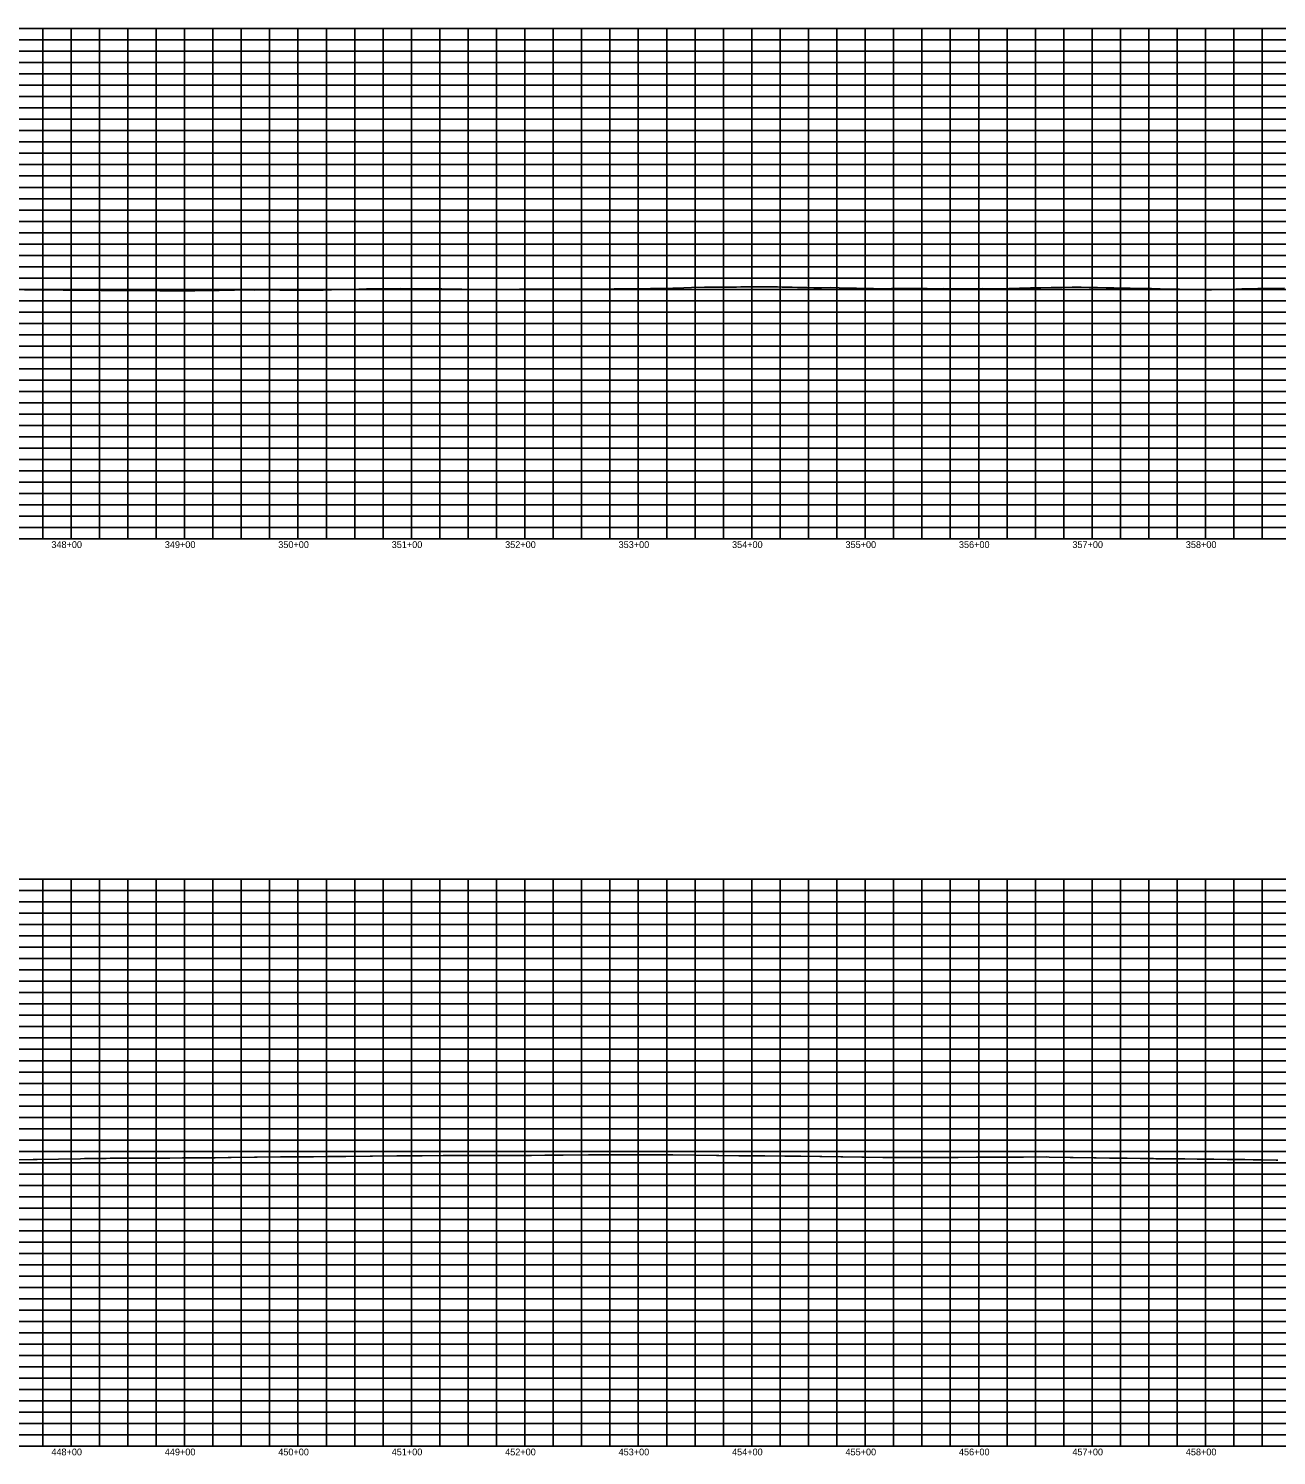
# Model space of a CAD drawing. Extents: x 1399671 to 1408349, y 1930471 to 1933387.
# Drawn here: x 1405087 to 1406187, y 1930471 to 1931729 of the extents above; entities that cross this region are included whole.
import ezdxf

# ---------------------------------------------------------------- set-up
doc = ezdxf.new("R2010")
doc.units = 0
for name, color, linetype in [('R_Exist Surface', 7, 'Continuous'), ('R_Grid', 7, 'Continuous'), ('R_Grid Annot', 7, 'Continuous')]:
    doc.layers.add(name, color=color, linetype=linetype)

msp = doc.modelspace()

# ---------------------------------------------------------------- linework, layer by layer
at = {"layer": 'R_Exist Surface'}
for points in [[(1405083.2, 1931498.2), (1405090.4, 1931498.1), (1405100.3, 1931498), (1405105.2, 1931498.2), (1405117.3, 1931498), (1405119.7, 1931498), (1405129.1, 1931497.8), (1405133.3, 1931497.9), (1405133.9, 1931497.8), (1405150.7, 1931497.6), (1405152.8, 1931497.6), (1405153, 1931497.6), (1405171, 1931497.6), (1405172.4, 1931497.6), (1405186.4, 1931497.5), (1405187.6, 1931497.5), (1405201.8, 1931497.5), (1405202.8, 1931497.4), (1405217.3, 1931497.4), (1405218, 1931497.4), (1405232.8, 1931497.3), (1405233.2, 1931497.3), (1405248.3, 1931497.5), (1405251.5, 1931497.6), (1405254.8, 1931497.7), (1405268.1, 1931498), (1405273.3, 1931498.2), (1405273.4, 1931498.2), (1405285.8, 1931497.9), (1405290.3, 1931498.1), (1405295.3, 1931498.1), (1405308.3, 1931497.8), (1405312.1, 1931497.8), (1405325.2, 1931497.9), (1405329.3, 1931497.9), (1405341.9, 1931497.9), (1405346.3, 1931497.9), (1405361, 1931498.5), (1405365.7, 1931498.6), (1405370.7, 1931498.6), (1405384.5, 1931499.1), (1405390, 1931499.2), (1405399.7, 1931499.2), (1405405.4, 1931499.2), (1405414.8, 1931499.3), (1405420.5, 1931499.2), (1405430.3, 1931499.2), (1405435.7, 1931499.2), (1405445.8, 1931499.2), (1405450.9, 1931499.2), (1405463.9, 1931498.8), (1405468.5, 1931498.8), (1405482.5, 1931498.5), (1405488.7, 1931498.5), (1405500.7, 1931498.6), (1405508.2, 1931498.6), (1405519.5, 1931498.7), (1405528.3, 1931498.7), (1405542.2, 1931498.7), (1405549.5, 1931498.7), (1405564.4, 1931498.7), (1405567.9, 1931498.7), (1405584.4, 1931498.9), (1405589, 1931498.9), (1405603, 1931499.1), (1405608.5, 1931499.1), (1405614.1, 1931499), (1405626.8, 1931499.2), (1405634.8, 1931499.4), (1405645.6, 1931499.5), (1405654.6, 1931499.8), (1405664.4, 1931500), (1405671.2, 1931500.2), (1405682.4, 1931500.5), (1405687.8, 1931500.6), (1405696.8, 1931500.6), (1405701.3, 1931500.7), (1405710.8, 1931500.7), (1405714.6, 1931500.8), (1405724.4, 1931500.8), (1405734.3, 1931500.9), (1405737.4, 1931500.8), (1405747, 1931500.8), (1405750.9, 1931500.6), (1405759.8, 1931500.7), (1405764.6, 1931500.4), (1405772.7, 1931500.4), (1405778.9, 1931500.1), (1405785.8, 1931500.1), (1405793.9, 1931500.2), (1405801.2, 1931499.9), (1405808.1, 1931499.6), (1405816.4, 1931499.7), (1405823.5, 1931499.4), (1405831.4, 1931499.5), (1405838.8, 1931499.2), (1405847.3, 1931499.3), (1405855, 1931499.3), (1405863.9, 1931499.4), (1405869.6, 1931499.3), (1405878.7, 1931499.3), (1405884.1, 1931499.2), (1405893.4, 1931499.3), (1405898.7, 1931499.2), (1405903.8, 1931499.1), (1405919.1, 1931499.1), (1405927.2, 1931499.3), (1405942.2, 1931499.2), (1405950.7, 1931499.4), (1405960.3, 1931499.6), (1405970, 1931499.9), (1405978.9, 1931500), (1405988.1, 1931500.2), (1405997.8, 1931500.4), (1406006.6, 1931500.6), (1406014.6, 1931500.5), (1406021.5, 1931500.4), (1406029, 1931500.2), (1406036.5, 1931500.1), (1406043.3, 1931500), (1406051.5, 1931499.8), (1406057.7, 1931499.7), (1406066.6, 1931499.5), (1406076.5, 1931499.3), (1406084.1, 1931499.1), (1406094.2, 1931498.9), (1406101.3, 1931498.7), (1406111.6, 1931498.5), (1406113.4, 1931498.4), (1406124.4, 1931498.2), (1406129.5, 1931498.2), (1406145.2, 1931498.5), (1406151, 1931498.9), (1406151, 1931498.9), (1406156.2, 1931499), (1406170.2, 1931499.3), (1406176.5, 1931499.3), (1406180.9, 1931499.3), (1406193.7, 1931499.6)], [(1405071.7, 1930731.2), (1405090.8, 1930731.5), (1405094.2, 1930731.5), (1405113.2, 1930731.9), (1405132.4, 1930732.1), (1405135.9, 1930732.2), (1405155.2, 1930732.4), (1405158.5, 1930732.5), (1405170.1, 1930732.5), (1405173.3, 1930732.5), (1405184.9, 1930732.6), (1405196.4, 1930732.6), (1405199.6, 1930732.6), (1405211.2, 1930732.7), (1405222.4, 1930732.8), (1405224.1, 1930732.8), (1405225.7, 1930732.8), (1405236.9, 1930732.9), (1405238.5, 1930732.9), (1405249.7, 1930733), (1405251.3, 1930733), (1405262.6, 1930733.1), (1405265.2, 1930733.1), (1405285.8, 1930733.4), (1405288.1, 1930733.4), (1405308.9, 1930733.7), (1405310.1, 1930733.7), (1405322.8, 1930733.8), (1405324, 1930733.8), (1405336.7, 1930733.9), (1405337.9, 1930733.9), (1405350.6, 1930734.1), (1405351.8, 1930734.1), (1405364.4, 1930734.2), (1405366.5, 1930734.2), (1405387.9, 1930734.5), (1405390, 1930734.5), (1405411.4, 1930734.7), (1405413.2, 1930734.7), (1405431.8, 1930734.8), (1405433.8, 1930734.8), (1405452.2, 1930734.9), (1405453.7, 1930734.9), (1405465.3, 1930734.9), (1405466.7, 1930734.9), (1405478.3, 1930734.9), (1405490.1, 1930734.9), (1405491.3, 1930734.9), (1405503.2, 1930734.9), (1405504.4, 1930734.9), (1405516.2, 1930735), (1405517.2, 1930735), (1405529, 1930735.1), (1405530.1, 1930735.1), (1405541.9, 1930735.3), (1405542.9, 1930735.3), (1405544, 1930735.3), (1405555.8, 1930735.4), (1405557.8, 1930735.4), (1405580.2, 1930735.5), (1405602.5, 1930735.5), (1405604.6, 1930735.5), (1405626.4, 1930735.5), (1405628.6, 1930735.5), (1405630.7, 1930735.5), (1405652.5, 1930735.5), (1405654.5, 1930735.5), (1405673.8, 1930735.2), (1405693, 1930735), (1405695.1, 1930735), (1405712.8, 1930734.8), (1405714.5, 1930734.8), (1405732.2, 1930734.6), (1405733.9, 1930734.6), (1405735.7, 1930734.6), (1405753.3, 1930734.5), (1405753.8, 1930734.5), (1405758.3, 1930734.4), (1405766.4, 1930734.5), (1405767.3, 1930734.5), (1405784.2, 1930734.2), (1405785.9, 1930734.2), (1405802.7, 1930733.9), (1405804.4, 1930733.9), (1405821.3, 1930733.6), (1405822.9, 1930733.6), (1405839.8, 1930733.3), (1405841.4, 1930733.2), (1405856.3, 1930733.3), (1405857.6, 1930733.3), (1405872.6, 1930733.3), (1405873.8, 1930733.3), (1405888.9, 1930733.3), (1405890, 1930733.3), (1405891, 1930733.3), (1405906.2, 1930733.3), (1405922.2, 1930733.4), (1405923.2, 1930733.4), (1405939.3, 1930733.6), (1405939.8, 1930733.6), (1405940.8, 1930733.6), (1405961.9, 1930733.6), (1405963.7, 1930733.6), (1405983.9, 1930733.7), (1405986.4, 1930733.6), (1406004.8, 1930733.3), (1406007.6, 1930733.2), (1406025.8, 1930732.8), (1406027.7, 1930732.8), (1406039.4, 1930732.7), (1406041.4, 1930732.6), (1406053, 1930732.5), (1406055, 1930732.5), (1406066.7, 1930732.3), (1406078.2, 1930732.2), (1406080.3, 1930732.1), (1406091.1, 1930732.1), (1406093.1, 1930732), (1406103.9, 1930732), (1406105.9, 1930732), (1406116.7, 1930731.9), (1406118.7, 1930731.9), (1406122.5, 1930731.8), (1406129.5, 1930731.8), (1406131.5, 1930731.8), (1406143.1, 1930731.6), (1406144.3, 1930731.6), (1406145.2, 1930731.6), (1406156.9, 1930731.4), (1406158.9, 1930731.4), (1406166.1, 1930731.2), (1406170.7, 1930731.2), (1406172.6, 1930731.2), (1406174.5, 1930731.1), (1406186.3, 1930731), (1406188, 1930730.9)]]:
    msp.add_lwpolyline(points, dxfattribs=at)
at = {"layer": 'R_Grid'}
for p, q in [((1400324.2, 1931728.6), (1408324.2, 1931728.6)), ((1400324.2, 1931728.6), (1408324.2, 1931728.6)), ((1405099.2, 1931278.6), (1405099.2, 1931728.6)), ((1405124.2, 1931278.6), (1405124.2, 1931728.6)), ((1405149.2, 1931278.6), (1405149.2, 1931728.6)), ((1405174.2, 1931278.6), (1405174.2, 1931728.6)), ((1405199.2, 1931278.6), (1405199.2, 1931728.6)), ((1405224.2, 1931278.6), (1405224.2, 1931728.6)), ((1405249.2, 1931278.6), (1405249.2, 1931728.6)), ((1405274.2, 1931278.6), (1405274.2, 1931728.6)), ((1405299.2, 1931278.6), (1405299.2, 1931728.6)), ((1405324.2, 1931278.6), (1405324.2, 1931728.6)), ((1405349.2, 1931278.6), (1405349.2, 1931728.6)), ((1405374.2, 1931278.6), (1405374.2, 1931728.6)), ((1405399.2, 1931278.6), (1405399.2, 1931728.6)), ((1405424.2, 1931278.6), (1405424.2, 1931728.6)), ((1405449.2, 1931278.6), (1405449.2, 1931728.6)), ((1405474.2, 1931278.6), (1405474.2, 1931728.6)), ((1405499.2, 1931278.6), (1405499.2, 1931728.6)), ((1405524.2, 1931278.6), (1405524.2, 1931728.6)), ((1405549.2, 1931278.6), (1405549.2, 1931728.6)), ((1405574.2, 1931278.6), (1405574.2, 1931728.6)), ((1405599.2, 1931278.6), (1405599.2, 1931728.6)), ((1405624.2, 1931278.6), (1405624.2, 1931728.6)), ((1405649.2, 1931278.6), (1405649.2, 1931728.6)), ((1405674.2, 1931278.6), (1405674.2, 1931728.6)), ((1405699.2, 1931278.6), (1405699.2, 1931728.6)), ((1405724.2, 1931278.6), (1405724.2, 1931728.6)), ((1405749.2, 1931278.6), (1405749.2, 1931728.6)), ((1405774.2, 1931278.6), (1405774.2, 1931728.6)), ((1405799.2, 1931278.6), (1405799.2, 1931728.6)), ((1405824.2, 1931278.6), (1405824.2, 1931728.6)), ((1405849.2, 1931278.6), (1405849.2, 1931728.6)), ((1405874.2, 1931278.6), (1405874.2, 1931728.6)), ((1405899.2, 1931278.6), (1405899.2, 1931728.6)), ((1405924.2, 1931278.6), (1405924.2, 1931728.6)), ((1405949.2, 1931278.6), (1405949.2, 1931728.6)), ((1405974.2, 1931278.6), (1405974.2, 1931728.6)), ((1405999.2, 1931278.6), (1405999.2, 1931728.6)), ((1406024.2, 1931278.6), (1406024.2, 1931728.6)), ((1406049.2, 1931278.6), (1406049.2, 1931728.6)), ((1406074.2, 1931278.6), (1406074.2, 1931728.6)), ((1406099.2, 1931278.6), (1406099.2, 1931728.6)), ((1406124.2, 1931278.6), (1406124.2, 1931728.6)), ((1406149.2, 1931278.6), (1406149.2, 1931728.6)), ((1406174.2, 1931278.6), (1406174.2, 1931728.6)), ((1400324.2, 1931718.6), (1408324.2, 1931718.6)), ((1400324.2, 1931708.6), (1408324.2, 1931708.6)), ((1400324.2, 1931698.6), (1408324.2, 1931698.6)), ((1400324.2, 1931688.6), (1408324.2, 1931688.6)), ((1400324.2, 1931678.6), (1408324.2, 1931678.6)), ((1400324.2, 1931668.6), (1408324.2, 1931668.6)), ((1400324.2, 1931658.6), (1408324.2, 1931658.6)), ((1400324.2, 1931648.6), (1408324.2, 1931648.6)), ((1400324.2, 1931638.6), (1408324.2, 1931638.6)), ((1400324.2, 1931628.6), (1408324.2, 1931628.6)), ((1400324.2, 1931618.6), (1408324.2, 1931618.6)), ((1400324.2, 1931608.6), (1408324.2, 1931608.6)), ((1400324.2, 1931598.6), (1408324.2, 1931598.6)), ((1400324.2, 1931588.6), (1408324.2, 1931588.6)), ((1400324.2, 1931578.6), (1408324.2, 1931578.6)), ((1400324.2, 1931568.6), (1408324.2, 1931568.6)), ((1400324.2, 1931558.6), (1408324.2, 1931558.6)), ((1400324.2, 1931548.6), (1408324.2, 1931548.6)), ((1400324.2, 1931538.6), (1408324.2, 1931538.6)), ((1400324.2, 1931528.6), (1408324.2, 1931528.6)), ((1400324.2, 1931518.6), (1408324.2, 1931518.6)), ((1400324.2, 1931508.6), (1408324.2, 1931508.6)), ((1400324.2, 1931498.6), (1408324.2, 1931498.6)), ((1400324.2, 1931488.6), (1408324.2, 1931488.6)), ((1400324.2, 1931478.6), (1408324.2, 1931478.6)), ((1400324.2, 1931468.6), (1408324.2, 1931468.6)), ((1400324.2, 1931458.6), (1408324.2, 1931458.6)), ((1400324.2, 1931448.6), (1408324.2, 1931448.6)), ((1400324.2, 1931438.6), (1408324.2, 1931438.6)), ((1400324.2, 1931428.6), (1408324.2, 1931428.6)), ((1400324.2, 1931418.6), (1408324.2, 1931418.6)), ((1400324.2, 1931408.6), (1408324.2, 1931408.6)), ((1400324.2, 1931398.6), (1408324.2, 1931398.6)), ((1400324.2, 1931388.6), (1408324.2, 1931388.6)), ((1400324.2, 1931378.6), (1408324.2, 1931378.6)), ((1400324.2, 1931368.6), (1408324.2, 1931368.6)), ((1400324.2, 1931358.6), (1408324.2, 1931358.6)), ((1400324.2, 1931348.6), (1408324.2, 1931348.6)), ((1400324.2, 1931338.6), (1408324.2, 1931338.6)), ((1400324.2, 1931328.6), (1408324.2, 1931328.6)), ((1400324.2, 1931318.6), (1408324.2, 1931318.6)), ((1400324.2, 1931308.6), (1408324.2, 1931308.6)), ((1400324.2, 1931298.6), (1408324.2, 1931298.6)), ((1400324.2, 1931288.6), (1408324.2, 1931288.6)), ((1400324.2, 1931278.6), (1408324.2, 1931278.6)), ((1400324.2, 1930978.6), (1407124.2, 1930978.6)), ((1400324.2, 1930978.6), (1407124.2, 1930978.6)), ((1405099.2, 1930478.6), (1405099.2, 1930978.6)), ((1405124.2, 1930478.6), (1405124.2, 1930978.6)), ((1405149.2, 1930478.6), (1405149.2, 1930978.6)), ((1405174.2, 1930478.6), (1405174.2, 1930978.6)), ((1405199.2, 1930478.6), (1405199.2, 1930978.6)), ((1405224.2, 1930478.6), (1405224.2, 1930978.6)), ((1405249.2, 1930478.6), (1405249.2, 1930978.6)), ((1405274.2, 1930478.6), (1405274.2, 1930978.6)), ((1405299.2, 1930478.6), (1405299.2, 1930978.6)), ((1405324.2, 1930478.6), (1405324.2, 1930978.6)), ((1405349.2, 1930478.6), (1405349.2, 1930978.6)), ((1405374.2, 1930478.6), (1405374.2, 1930978.6)), ((1405399.2, 1930478.6), (1405399.2, 1930978.6)), ((1405424.2, 1930478.6), (1405424.2, 1930978.6)), ((1405449.2, 1930478.6), (1405449.2, 1930978.6)), ((1405474.2, 1930478.6), (1405474.2, 1930978.6)), ((1405499.2, 1930478.6), (1405499.2, 1930978.6)), ((1405524.2, 1930478.6), (1405524.2, 1930978.6)), ((1405549.2, 1930478.6), (1405549.2, 1930978.6)), ((1405574.2, 1930478.6), (1405574.2, 1930978.6)), ((1405599.2, 1930478.6), (1405599.2, 1930978.6)), ((1405624.2, 1930478.6), (1405624.2, 1930978.6)), ((1405649.2, 1930478.6), (1405649.2, 1930978.6)), ((1405674.2, 1930478.6), (1405674.2, 1930978.6)), ((1405699.2, 1930478.6), (1405699.2, 1930978.6)), ((1405724.2, 1930478.6), (1405724.2, 1930978.6)), ((1405749.2, 1930478.6), (1405749.2, 1930978.6)), ((1405774.2, 1930478.6), (1405774.2, 1930978.6)), ((1405799.2, 1930478.6), (1405799.2, 1930978.6)), ((1405824.2, 1930478.6), (1405824.2, 1930978.6)), ((1405849.2, 1930478.6), (1405849.2, 1930978.6)), ((1405874.2, 1930478.6), (1405874.2, 1930978.6)), ((1405899.2, 1930478.6), (1405899.2, 1930978.6)), ((1405924.2, 1930478.6), (1405924.2, 1930978.6)), ((1405949.2, 1930478.6), (1405949.2, 1930978.6)), ((1405974.2, 1930478.6), (1405974.2, 1930978.6)), ((1405999.2, 1930478.6), (1405999.2, 1930978.6)), ((1406024.2, 1930478.6), (1406024.2, 1930978.6)), ((1406049.2, 1930478.6), (1406049.2, 1930978.6)), ((1406074.2, 1930478.6), (1406074.2, 1930978.6)), ((1406099.2, 1930478.6), (1406099.2, 1930978.6)), ((1406124.2, 1930478.6), (1406124.2, 1930978.6)), ((1406149.2, 1930478.6), (1406149.2, 1930978.6)), ((1406174.2, 1930478.6), (1406174.2, 1930978.6)), ((1400324.2, 1930968.6), (1407124.2, 1930968.6)), ((1400324.2, 1930958.6), (1407124.2, 1930958.6)), ((1400324.2, 1930948.6), (1407124.2, 1930948.6)), ((1400324.2, 1930938.6), (1407124.2, 1930938.6)), ((1400324.2, 1930928.6), (1407124.2, 1930928.6)), ((1400324.2, 1930918.6), (1407124.2, 1930918.6)), ((1400324.2, 1930908.6), (1407124.2, 1930908.6)), ((1400324.2, 1930898.6), (1407124.2, 1930898.6)), ((1400324.2, 1930888.6), (1407124.2, 1930888.6)), ((1400324.2, 1930878.6), (1407124.2, 1930878.6)), ((1400324.2, 1930868.6), (1407124.2, 1930868.6)), ((1400324.2, 1930858.6), (1407124.2, 1930858.6)), ((1400324.2, 1930848.6), (1407124.2, 1930848.6)), ((1400324.2, 1930838.6), (1407124.2, 1930838.6)), ((1400324.2, 1930828.6), (1407124.2, 1930828.6)), ((1400324.2, 1930818.6), (1407124.2, 1930818.6)), ((1400324.2, 1930808.6), (1407124.2, 1930808.6)), ((1400324.2, 1930798.6), (1407124.2, 1930798.6)), ((1400324.2, 1930788.6), (1407124.2, 1930788.6)), ((1400324.2, 1930778.6), (1407124.2, 1930778.6)), ((1400324.2, 1930768.6), (1407124.2, 1930768.6)), ((1400324.2, 1930758.6), (1407124.2, 1930758.6)), ((1400324.2, 1930748.6), (1407124.2, 1930748.6)), ((1400324.2, 1930738.6), (1407124.2, 1930738.6)), ((1400324.2, 1930728.6), (1407124.2, 1930728.6)), ((1400324.2, 1930718.6), (1407124.2, 1930718.6)), ((1400324.2, 1930708.6), (1407124.2, 1930708.6)), ((1400324.2, 1930698.6), (1407124.2, 1930698.6)), ((1400324.2, 1930688.6), (1407124.2, 1930688.6)), ((1400324.2, 1930678.6), (1407124.2, 1930678.6)), ((1400324.2, 1930668.6), (1407124.2, 1930668.6)), ((1400324.2, 1930658.6), (1407124.2, 1930658.6)), ((1400324.2, 1930648.6), (1407124.2, 1930648.6)), ((1400324.2, 1930638.6), (1407124.2, 1930638.6)), ((1400324.2, 1930628.6), (1407124.2, 1930628.6)), ((1400324.2, 1930618.6), (1407124.2, 1930618.6)), ((1400324.2, 1930608.6), (1407124.2, 1930608.6)), ((1400324.2, 1930598.6), (1407124.2, 1930598.6)), ((1400324.2, 1930588.6), (1407124.2, 1930588.6)), ((1400324.2, 1930578.6), (1407124.2, 1930578.6)), ((1400324.2, 1930568.6), (1407124.2, 1930568.6)), ((1400324.2, 1930558.6), (1407124.2, 1930558.6)), ((1400324.2, 1930548.6), (1407124.2, 1930548.6)), ((1400324.2, 1930538.6), (1407124.2, 1930538.6)), ((1400324.2, 1930528.6), (1407124.2, 1930528.6)), ((1400324.2, 1930518.6), (1407124.2, 1930518.6)), ((1400324.2, 1930508.6), (1407124.2, 1930508.6)), ((1400324.2, 1930498.6), (1407124.2, 1930498.6)), ((1400324.2, 1930488.6), (1407124.2, 1930488.6)), ((1400324.2, 1930478.6), (1407124.2, 1930478.6))]:
    msp.add_line(p, q, dxfattribs=at)

# ---------------------------------------------------------------- texts
at = {"layer": 'R_Grid Annot'}
for s, p in [('348+00', (1405106.8, 1931270.6)), ('349+00', (1405206.8, 1931270.6)), ('350+00', (1405306.8, 1931270.6)), ('351+00', (1405406.8, 1931270.6)), ('352+00', (1405506.8, 1931270.6)), ('353+00', (1405606.8, 1931270.6)), ('354+00', (1405706.8, 1931270.6)), ('355+00', (1405806.8, 1931270.6)), ('356+00', (1405906.8, 1931270.6)), ('357+00', (1406006.8, 1931270.6)), ('358+00', (1406106.8, 1931270.6)), ('448+00', (1405106.8, 1930470.6)), ('449+00', (1405206.8, 1930470.6)), ('450+00', (1405306.8, 1930470.6)), ('451+00', (1405406.8, 1930470.6)), ('452+00', (1405506.8, 1930470.6)), ('453+00', (1405606.8, 1930470.6)), ('454+00', (1405706.8, 1930470.6)), ('455+00', (1405806.8, 1930470.6)), ('456+00', (1405906.8, 1930470.6)), ('457+00', (1406006.8, 1930470.6)), ('458+00', (1406106.8, 1930470.6))]:
    msp.add_text(s, height=6, dxfattribs=at).set_placement(p)

doc.saveas('drawing.dxf')
